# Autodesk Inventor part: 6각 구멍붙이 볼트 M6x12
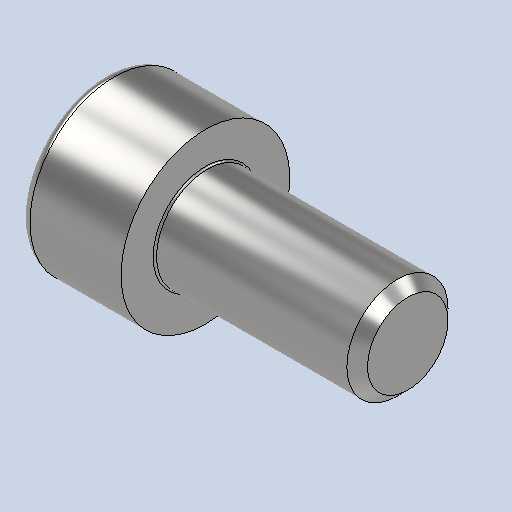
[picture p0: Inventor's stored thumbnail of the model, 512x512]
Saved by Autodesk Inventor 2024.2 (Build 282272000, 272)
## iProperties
Created: 2025-09
Part Number: 6각 구멍붙이 볼트 M6x12
Material: 강철, 연강
Description: 6각머리 태핑 나사
Document SubType Name: Modeling
Designer: home
Density: 7.85 g/cm^3
Appearance: 기본값
Author: jhkim
Sending System: Autodesk Inventor 2026
Preprocessor: ST-DEVELOPER v20.1
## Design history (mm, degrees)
feature "Solid1"
node "솔리드1"
